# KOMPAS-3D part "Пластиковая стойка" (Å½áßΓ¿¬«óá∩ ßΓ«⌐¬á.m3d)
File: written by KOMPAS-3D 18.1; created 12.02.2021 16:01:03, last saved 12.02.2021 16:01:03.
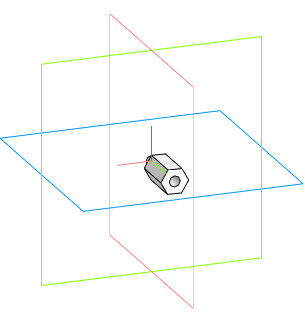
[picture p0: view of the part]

Document properties: Полное имя файла: E:\Столик\Пластиковая стойка.m3d

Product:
- Part/product: Пластиковая стойка

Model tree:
1. Операция без истории:1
